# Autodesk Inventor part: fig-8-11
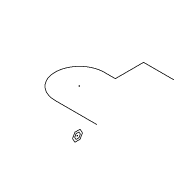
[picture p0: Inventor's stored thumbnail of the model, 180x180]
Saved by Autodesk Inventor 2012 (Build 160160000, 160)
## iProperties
Created: 2004-05
Part Number: fig-8-11
Document SubType Name: Modeling
Designer: CADCIM Technologies
Manufacturer: Standard
Standards Organization: Custom
Density: 1 g/cm^3
Material: Default
Author: CADCIM Technologies
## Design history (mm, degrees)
sketch "Sketch1"
  geometry: L1 (-42.583, 3.219)-(-90.066, 3.219); L2 (-90.066, 58.92)-(-77.282, 58.92); L3 (-77.282, 58.92)-(-77.282, 91.063); L4 (-77.282, 91.063)-(-42.583, 91.063); A1 r 27.851 centre (-90.066, 31.07) between (-90.066, 58.92) and (-90.066, 3.219)
  constraints: 8 end point, 2 parallel, 2 point on circle, 2 tangent, 1 centre point, 1 perpendicular
workplane "Work Plane2"
sketch "Sketch2"
  geometry: L1 (16.303, 0)-(19.151, 4.934); L2 (19.151, 4.934)-(24.849, 4.934); L3 (24.849, 4.934)-(27.697, 0); L4 (27.697, 0)-(24.849, -4.934); L5 (24.849, -4.934)-(19.151, -4.934); L6 (19.151, -4.934)-(16.303, 0); L7 (18.744, 0)-(20.372, 2.819); L8 (20.372, 2.819)-(23.628, 2.819); L9 (23.628, 2.819)-(25.256, 0); L10 (25.256, 0)-(23.628, -2.819); L11 (23.628, -2.819)-(20.372, -2.819); L12 (20.372, -2.819)-(18.744, 0); 2 further points
  constraints: 24 end point, 1 coincident, 22 other
